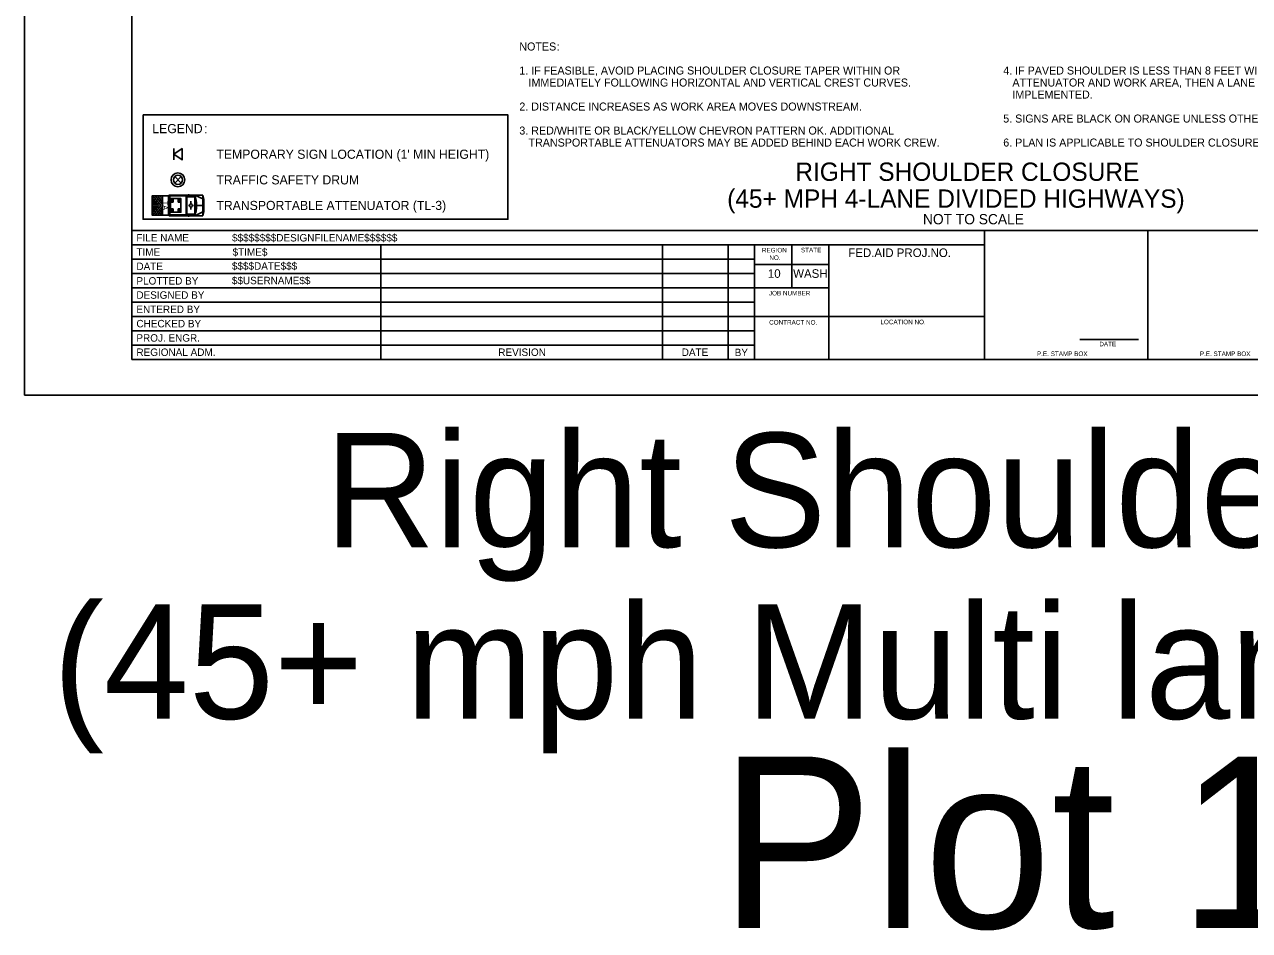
# Model space of a CAD drawing. Extents: x 99999.1 to 100055.7, y 99995 to 100013.2.
# Drawn here: x 99999.06 to 100009.77, y 99995.01 to 100002.93 of the extents above; entities that cross this region are included whole.
import ezdxf

# ---------------------------------------------------------------- set-up
doc = ezdxf.new("R2010")
doc.units = 0
for name, color, linetype in [('SH_DE_DetailHeading1Text', 7, 'Continuous'), ('SH_GI_GeneralNotesBodyText', 7, 'Continuous'), ('SH_GI_PlotLimits', 7, 'Continuous'), ('SH_GI_SheetBorder', 7, 'Continuous'), ('SH_GI_SheetLocationText', 7, 'Continuous'), ('SH_GI_SheetTextInCells', 7, 'Continuous'), ('SH_GI_TitleBlockText', 7, 'Continuous'), ('TR_WZ_PortableSignMountBlk-Wht', 7, 'Continuous'), ('TR_WZ_TrafficSafetyDrum', 7, 'Continuous'), ('TR_WZ_TransportableAttenuator', 7, 'Continuous'), ('TR_WZ_WorkZoneTextCurrent', 7, 'Continuous')]:
    doc.layers.add(name, color=color, linetype=linetype)

msp = doc.modelspace()

# ---------------------------------------------------------------- linework, layer by layer
at = {"layer": 'SH_GI_PlotLimits'}
msp.add_lwpolyline([(99999.062, 99999.687), (100016.062, 99999.687), (100016.062, 100010.687), (99999.062, 100010.687)], close=True, dxfattribs=at)
at = {"layer": 'SH_GI_SheetBorder'}
for p, q in [((100000, 100010.375), (100000, 100000)), ((100000, 100001.126), (100015.75, 100001.126)), ((100007.457, 100000), (100007.457, 100001.126)), ((100008.883, 100000), (100008.883, 100001.126)), ((100000, 100001.001), (100007.457, 100001.001)), ((100002.179, 100001.001), (100002.179, 100000)), ((100004.641, 100001.001), (100004.641, 100000)), ((100005.216, 100001.001), (100005.216, 100000)), ((100005.445, 100001.001), (100005.445, 100000)), ((100005.772, 100000.625), (100005.772, 100001.001)), ((100006.096, 100000), (100006.096, 100001.001)), ((100000, 100000.876), (100002.182, 100000.876)), ((100002.182, 100000.876), (100005.447, 100000.876)), ((100006.096, 100000.831), (100005.447, 100000.831)), ((100000, 100000.751), (100002.182, 100000.751)), ((100002.182, 100000.751), (100005.447, 100000.751)), ((100000, 100000.625), (100005.447, 100000.625)), ((100006.096, 100000.625), (100005.447, 100000.625)), ((100000, 100000.5), (100005.447, 100000.5)), ((100000, 100000.375), (100005.447, 100000.375)), ((100007.457, 100000.375), (100005.447, 100000.375)), ((100000, 100000.25), (100005.447, 100000.25)), ((100008.29, 100000.173), (100008.802, 100000.173)), ((100000, 100000.125), (100005.447, 100000.125)), ((100000, 100000), (100015.75, 100000))]:
    msp.add_line(p, q, dxfattribs=at)
at = {"layer": 'TR_WZ_PortableSignMountBlk-Wht'}
msp.add_line((100000.368, 100001.744), (100000.368, 100001.844), dxfattribs=at)
msp.add_lwpolyline([(100000.368, 100001.794), (100000.44, 100001.844), (100000.44, 100001.744)], close=True, dxfattribs=at)
at = {"layer": 'TR_WZ_TrafficSafetyDrum'}
for p, q in [((100000.432, 100001.598), (100000.376, 100001.542)), ((100000.432, 100001.542), (100000.376, 100001.598))]:
    msp.add_line(p, q, dxfattribs=at)
for radius in [0.06, 0.06, 0.04]:
    msp.add_circle((100000.404, 100001.57), radius, dxfattribs=at)
at = {"layer": 'TR_WZ_TransportableAttenuator'}
for p, q in [((100000.179, 100001.414), (100000.235, 100001.347)), ((100000.179, 100001.393), (100000.179, 100001.414)), ((100000.235, 100001.347), (100000.179, 100001.414)), ((100000.179, 100001.414), (100000.179, 100001.393)), ((100000.217, 100001.347), (100000.179, 100001.393)), ((100000.179, 100001.393), (100000.217, 100001.347)), ((100000.179, 100001.369), (100000.199, 100001.346)), ((100000.179, 100001.323), (100000.179, 100001.369)), ((100000.199, 100001.346), (100000.179, 100001.369)), ((100000.179, 100001.369), (100000.179, 100001.323)), ((100000.235, 100001.347), (100000.179, 100001.279)), ((100000.179, 100001.301), (100000.217, 100001.347)), ((100000.217, 100001.347), (100000.179, 100001.301)), ((100000.179, 100001.279), (100000.235, 100001.347)), ((100000.199, 100001.346), (100000.179, 100001.323)), ((100000.179, 100001.323), (100000.199, 100001.346)), ((100000.255, 100001.346), (100000.185, 100001.431)), ((100000.185, 100001.431), (100000.204, 100001.431)), ((100000.185, 100001.431), (100000.255, 100001.346)), ((100000.204, 100001.431), (100000.185, 100001.431)), ((100000.185, 100001.261), (100000.255, 100001.346)), ((100000.255, 100001.346), (100000.185, 100001.261)), ((100000.204, 100001.431), (100000.268, 100001.354)), ((100000.268, 100001.354), (100000.204, 100001.431)), ((100000.268, 100001.378), (100000.225, 100001.431)), ((100000.225, 100001.431), (100000.244, 100001.431)), ((100000.244, 100001.431), (100000.225, 100001.431)), ((100000.225, 100001.431), (100000.268, 100001.378)), ((100000.244, 100001.431), (100000.268, 100001.402)), ((100000.268, 100001.402), (100000.244, 100001.431)), ((100000.268, 100001.262), (100000.268, 100001.431)), ((100000.328, 100001.431), (100000.268, 100001.431)), ((100000.268, 100001.402), (100000.268, 100001.378)), ((100000.268, 100001.378), (100000.268, 100001.402)), ((100000.268, 100001.354), (100000.268, 100001.338)), ((100000.268, 100001.338), (100000.268, 100001.354)), ((100000.321, 100001.427), (100000.321, 100001.264)), ((100000.321, 100001.359), (100000.327, 100001.355)), ((100000.323, 100001.346), (100000.326, 100001.346)), ((100000.324, 100001.433), (100000.327, 100001.433)), ((100000.324, 100001.348), (100000.324, 100001.343)), ((100000.327, 100001.433), (100000.327, 100001.259)), ((100000.328, 100001.436), (100000.48, 100001.436)), ((100000.328, 100001.436), (100000.328, 100001.256)), ((100000.328, 100001.43), (100000.328, 100001.262)), ((100000.332, 100001.429), (100000.332, 100001.263)), ((100000.332, 100001.429), (100000.476, 100001.429)), ((100000.476, 100001.429), (100000.476, 100001.263)), ((100000.48, 100001.436), (100000.48, 100001.256)), ((100000.482, 100001.436), (100000.482, 100001.256)), ((100000.622, 100001.436), (100000.482, 100001.436)), ((100000.551, 100001.422), (100000.482, 100001.422)), ((100000.501, 100001.438), (100000.493, 100001.438)), ((100000.495, 100001.346), (100000.504, 100001.346)), ((100000.507, 100001.346), (100000.507, 100001.346)), ((100000.517, 100001.382), (100000.517, 100001.367)), ((100000.54, 100001.346), (100000.53, 100001.346)), ((100000.551, 100001.436), (100000.542, 100001.422)), ((100000.551, 100001.436), (100000.551, 100001.256)), ((100000.552, 100001.436), (100000.552, 100001.256)), ((100000.622, 100001.403), (100000.552, 100001.436)), ((100000.622, 100001.346), (100000.566, 100001.346)), ((100000.622, 100001.436), (100000.622, 100001.256)), ((100000.622, 100001.436), (100000.629, 100001.4)), ((100000.629, 100001.4), (100000.629, 100001.292)), ((100000.179, 100001.279), (100000.179, 100001.301)), ((100000.179, 100001.301), (100000.179, 100001.279)), ((100000.204, 100001.261), (100000.185, 100001.261)), ((100000.185, 100001.261), (100000.204, 100001.261)), ((100000.268, 100001.338), (100000.204, 100001.261)), ((100000.204, 100001.261), (100000.268, 100001.338)), ((100000.224, 100001.261), (100000.268, 100001.314)), ((100000.268, 100001.314), (100000.224, 100001.261)), ((100000.245, 100001.261), (100000.224, 100001.261)), ((100000.224, 100001.261), (100000.245, 100001.261)), ((100000.268, 100001.289), (100000.245, 100001.261)), ((100000.245, 100001.261), (100000.268, 100001.289)), ((100000.268, 100001.314), (100000.268, 100001.289)), ((100000.268, 100001.289), (100000.268, 100001.314)), ((100000.328, 100001.262), (100000.268, 100001.262)), ((100000.321, 100001.333), (100000.327, 100001.337)), ((100000.324, 100001.259), (100000.327, 100001.259)), ((100000.328, 100001.256), (100000.48, 100001.256)), ((100000.332, 100001.263), (100000.476, 100001.263)), ((100000.551, 100001.27), (100000.482, 100001.27)), ((100000.622, 100001.256), (100000.482, 100001.256)), ((100000.501, 100001.253), (100000.493, 100001.253)), ((100000.517, 100001.31), (100000.517, 100001.325)), ((100000.544, 100001.27), (100000.551, 100001.256)), ((100000.622, 100001.289), (100000.552, 100001.256)), ((100000.622, 100001.256), (100000.629, 100001.292))]:
    msp.add_line(p, q, dxfattribs=at)
for points in [[(100000.268, 100001.261), (100000.179, 100001.261), (100000.179, 100001.431), (100000.268, 100001.431)], [(100000.34, 100001.406), (100000.43, 100001.406), (100000.43, 100001.286), (100000.34, 100001.286)], [(100000.347, 100001.398), (100000.362, 100001.398), (100000.362, 100001.376), (100000.347, 100001.376)], [(100000.422, 100001.398), (100000.407, 100001.398), (100000.407, 100001.376), (100000.422, 100001.376)], [(100000.347, 100001.316), (100000.362, 100001.316), (100000.362, 100001.293), (100000.347, 100001.293)], [(100000.422, 100001.316), (100000.407, 100001.316), (100000.407, 100001.293), (100000.422, 100001.293)]]:
    msp.add_lwpolyline(points, close=True, dxfattribs=at)
msp.add_lwpolyline([(100000.268, 100001.431), (100000.179, 100001.431), (100000.179, 100001.261), (100000.268, 100001.262)], dxfattribs=at)
for centre, major_axis, start_param, end_param in [((100000.324, 100001.427), (0, 0.00549), 6.283185, 7.853982), ((100000.452, 100001.346), (0, 0.189), 4.215852, 5.209111), ((100000.324, 100001.264), (0, -0.00549), 4.712389, 6.283185)]:
    msp.add_ellipse(centre, major_axis=major_axis, ratio=0.60201, start_param=start_param, end_param=end_param, dxfattribs=at)
for centre, major_axis in [((100000.324, 100001.346), (0, -0.00254)), ((100000.517, 100001.346), (0, -0.0173))]:
    msp.add_ellipse(centre, major_axis=major_axis, ratio=0.60201, dxfattribs=at)
at = {"layer": 'TR_WZ_WorkZoneTextCurrent'}
msp.add_lwpolyline([(100000.1, 100002.138), (100003.289, 100002.138), (100003.289, 100001.226), (100000.1, 100001.226)], close=True, dxfattribs=at)

# ---------------------------------------------------------------- texts
at = {"layer": 'SH_DE_DetailHeading1Text'}
for s, height, p in [('RIGHT SHOULDER CLOSURE', 0.16, (100005.802, 100001.561)), ('(45+ MPH 4-LANE DIVIDED HIGHWAYS)', 0.16, (100005.206, 100001.326)), ('NOT TO SCALE', 0.09, (100006.918, 100001.181))]:
    msp.add_text(s, height=height, rotation=360, dxfattribs=at).set_placement(p)
at = {"layer": 'SH_GI_GeneralNotesBodyText'}
for s, p in [('NOTES', (100003.389, 100002.701)), (':', (100003.716, 100002.701)), ('1. IF FEASIBLE, AVOID PLACING SHOULDER CLOSURE TAPER WITHIN OR ', (100003.389, 100002.491)), ('4. IF PAVED SHOULDER IS LESS THAN 8 FEET WIDE AT TRANSPORTABLE ', (100007.62, 100002.491)), ('IMMEDIATELY FOLLOWING HORIZONTAL AND VERTICAL CREST CURVES.', (100003.469, 100002.386)), ('ATTENUATOR AND WORK AREA, THEN A LANE CLOSURE SHALL BE ', (100007.7, 100002.386)), ('IMPLEMENTED.', (100007.7, 100002.281)), ('2. DISTANCE INCREASES AS WORK AREA MOVES DOWNSTREAM.', (100003.389, 100002.176)), ('5. SIGNS ARE BLACK ON ORANGE UNLESS OTHERWISE INDICATED.', (100007.62, 100002.071)), ('3. RED/WHITE OR BLACK/YELLOW CHEVRON PATTERN OK. ADDITIONAL ', (100003.389, 100001.966)), ('TRANSPORTABLE ATTENUATORS MAY BE ADDED BEHIND EACH WORK CREW.', (100003.469, 100001.861)), ('6. PLAN IS APPLICABLE TO SHOULDER CLOSURES OF 7 DAYS OR LESS.', (100007.62, 100001.861))]:
    msp.add_text(s, height=0.07, rotation=360, dxfattribs=at).set_placement(p)
at = {"layer": 'SH_GI_SheetLocationText'}
for s, height, p in [('Right Shoulder Closure', 1, (100001.687, 99998.357)), ('(45+ mph Multi lane Highways)', 1, (99999.311, 99996.857)), ('Plot 1', 1.5, (100005.142, 99995.027))]:
    msp.add_text(s, height=height, dxfattribs=at).set_placement(p)
at = {"layer": 'SH_GI_SheetTextInCells'}
for s, height, p in [('FILE NAME', 0.0651, (100000.041, 100001.031)), ('TIME', 0.0651, (100000.041, 100000.906)), ('REGION', 0.04, (100005.51, 100000.935)), ('STATE', 0.04, (100005.851, 100000.936)), ('FED.AID PROJ.NO.', 0.07506, (100006.265, 100000.895)), ('DATE', 0.0651, (100000.041, 100000.781)), ('NO.', 0.04, (100005.575, 100000.869)), ('PLOTTED BY', 0.0651, (100000.041, 100000.654)), ('10', 0.0751, (100005.562, 100000.713)), ('WASH', 0.0751, (100005.783, 100000.713)), ('DESIGNED BY', 0.06505, (100000.041, 100000.53)), ('JOB NUMBER', 0.04, (100005.571, 100000.559)), ('ENTERED BY', 0.0651, (100000.041, 100000.405)), ('CHECKED BY', 0.0651, (100000.041, 100000.28)), ('CONTRACT NO.', 0.04003, (100005.573, 100000.304)), ('LOCATION NO.', 0.04003, (100006.546, 100000.307)), ('PROJ. ENGR.', 0.06505, (100000.041, 100000.155)), ('REGIONAL ADM.', 0.06505, (100000.041, 100000.03)), ('REVISION', 0.0651, (100003.205, 100000.03)), ('DATE', 0.0651, (100004.809, 100000.03)), ('BY', 0.0651, (100005.272, 100000.028)), ('P.E. STAMP BOX', 0.04003, (100007.915, 100000.029)), ('DATE', 0.04, (100008.46, 100000.114)), ('P.E. STAMP BOX', 0.04003, (100009.339, 100000.029))]:
    msp.add_text(s, height=height, dxfattribs=at).set_placement(p)
at = {"layer": 'SH_GI_TitleBlockText'}
for s, height, p in [('$$$$$$$$DESIGNFILENAME$$$$$$', 0.06505, (100000.877, 100001.031)), ('$TIME$', 0.0651, (100000.882, 100000.906)), ('$$$$DATE$$$', 0.06505, (100000.876, 100000.784)), ('$$USERNAME$$', 0.06505, (100000.876, 100000.657))]:
    msp.add_text(s, height=height, dxfattribs=at).set_placement(p)
at = {"layer": 'TR_WZ_TransportableAttenuator'}
msp.add_text('TA', height=0.045, rotation=270, dxfattribs=at).set_placement((100000.272, 100001.385))
at = {"layer": 'TR_WZ_WorkZoneTextCurrent'}
for s, p in [('LEGEND', (100000.18, 100001.978)), (':', (100000.633, 100001.978)), ("TEMPORARY SIGN LOCATION (1' MIN HEIGHT)", (100000.74, 100001.754)), ('TRAFFIC SAFETY DRUM', (100000.74, 100001.53)), ('TRANSPORTABLE ATTENUATOR (TL-3)', (100000.74, 100001.306))]:
    msp.add_text(s, height=0.08, rotation=360, dxfattribs=at).set_placement(p)

doc.saveas('drawing.dxf')
